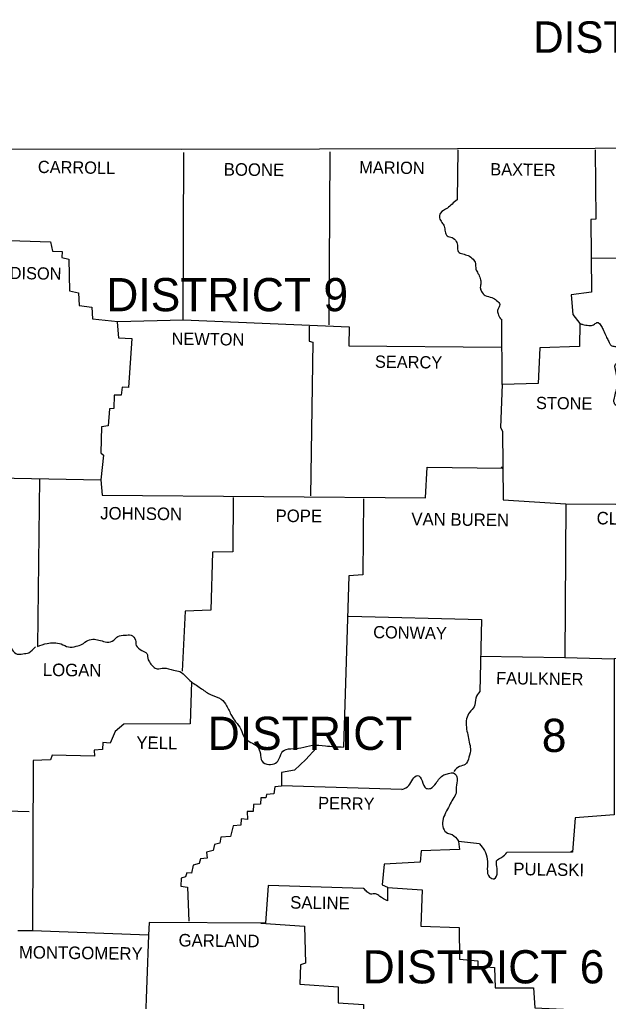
# Model space of a CAD drawing. Extents: x -12863 to 18921, y -8840 to 11152.
# Drawn here: x 11783 to 13760, y 7447 to 10747 of the extents above; entities that cross this region are included whole.
import ezdxf

# ---------------------------------------------------------------- set-up
doc = ezdxf.new("R2010")
doc.units = 0
for name, color, linetype in [('Level 1', 7, 'Continuous'), ('Level 2', 7, 'Continuous'), ('Level 3', 7, 'Continuous'), ('Level 42', 7, 'Continuous')]:
    doc.layers.add(name, color=color, linetype=linetype)

msp = doc.modelspace()

# ---------------------------------------------------------------- linework, layer by layer
at = {"layer": 'Level 1'}
for points in [[(10745.4, 10313), (12327.5, 10312), (13715.8, 10314.9), (15353.7, 10340.4), (16112.9, 10358)], [(14544.5, 10327.8), (14546.5, 10081.1), (14419.3, 10074.3), (14415.4, 9941.2), (13702.7, 9945.1)], [(11646.5, 10007.7), (11887.2, 9999.9), (11893.1, 9968.6), (11926.3, 9967.6), (11925.3, 9948), (11948.8, 9942.2), (11950.8, 9835.5), (11981.1, 9828.7), (11983.1, 9786.6), (12026.1, 9780.7), (12028.1, 9741.6), (12113.2, 9732.8), (12332.4, 9737.7), (12334.3, 10300.3)], [(12824.5, 10302.2), (12821.6, 9721.1)], [(13255, 10309.1), (13253, 10141.8)], [(13715.8, 10309.1), (13717.8, 10076.2), (13701.2, 10075.2), (13704.1, 9831.6), (13635.6, 9821.8), (13641.5, 9756.3), (13665, 9725.9), (13663, 9648.7), (13529.9, 9643.8), (13525, 9524.4), (13403.7, 9520.5), (13397.9, 9375.7), (13404.7, 9363.9), (13407.6, 9133), (13617, 9119.3), (13614.1, 8603.7), (13780.4, 8598.8), (13780.4, 8074.4), (13649.3, 8064.6), (13639.5, 7949.2), (13419.4, 7948.2)], [(10822.7, 9721.1), (11005.6, 9720.1), (11010.5, 9784.6), (11078, 9784.6), (11083.9, 9889.3), (11465.5, 9875.6), (11477.2, 9905), (11634.8, 9906), (11555.5, 9679), (11539.9, 9316), (11528.1, 9315), (11522.2, 9205.4), (11580, 9200.5), (11588.8, 9209.3), (12055.5, 9200.5), (12060.4, 9148.7)], [(12332.4, 9737.7), (12890.1, 9714.2), (12889.1, 9650.6), (13400.8, 9646.7)], [(13403.7, 9520.5), (13402.7, 9740.6)], [(12111.2, 9730.8), (12115.2, 9678), (12160.2, 9675.1), (12148.4, 9510.7), (12127.9, 9511.7), (12124, 9485.3), (12100.5, 9485.3), (12099.5, 9440.2), (12084.8, 9439.3), (12079.9, 9381.5), (12058.4, 9378.6), (12055.5, 9290.6), (12065.3, 9283.7), (12055.5, 9200.5)], [(12756, 9717.1), (12755, 9666.3), (12767.8, 9663.3), (12759.9, 9146.7)], [(12060.4, 9148.7), (13146.4, 9139.9), (13151.3, 9242.6), (13403.7, 9239.7)], [(13400.8, 9240.7), (13403.7, 9243.6)], [(11850, 9204.5), (11843.2, 8639.9)], [(12499.7, 9140.9), (12498.7, 8957.9), (12431.2, 8956.9), (12425.3, 8762.2), (12339.2, 8759.3), (12329.4, 8557.7)], [(12938, 9136), (12936, 8881.6), (12889.1, 8877.7), (12870.5, 8302.4)], [(13617, 9119.3), (14119.9, 9116.4), (14163, 9136.9), (14160, 8754.4), (14130.7, 8741.7), (14104.3, 8719.2), (14095.5, 8710.4), (14094.5, 8600.8), (13780.4, 8598.8)], [(12887.1, 8741.7), (13334.3, 8730.9), (13328.4, 8489.2)], [(11716.9, 8671.2), (11710.1, 8531.3), (11582.9, 8530.3), (11576.1, 8403.1), (11449.8, 8406.1), (11445.9, 8275), (11313.8, 8274), (11309.9, 8142.9), (11393.1, 8138), (11390.2, 8097.9), (11814.8, 8086.1)], [(13329.4, 8607.6), (13614.1, 8603.7)], [(12359.8, 8521.5), (12355.8, 8380.6), (12132.8, 8379.7), (12103.4, 8354.2), (12086.8, 8315.1), (12062.3, 8317), (12061.3, 8294.5), (12033, 8291.6), (12034, 8271.1), (11892.1, 8275), (11887.2, 8259.3), (11828.5, 8257.4), (11826.5, 7685), (11777.6, 7684)], [(12779.5, 8298.4), (12744.3, 8260.3), (12706.1, 8224.1), (12662.1, 8217.2), (12662.1, 8171.3), (12640.6, 8168.3), (12636.7, 8144.8), (12612.2, 8142.9), (12610.2, 8132.1), (12593.6, 8131.1), (12592.6, 8110.6), (12569.1, 8109.6), (12567.2, 8086.1), (12547.6, 8086.1), (12548.6, 8058.7), (12527.1, 8060.7), (12526.1, 8039.2), (12499.7, 8037.2), (12491.8, 8002), (12458.6, 7999.1), (12455.6, 7979.5), (12438, 7974.6), (12433.1, 7954), (12410.6, 7949.2), (12412.6, 7928.6), (12390.1, 7926.7), (12386.2, 7911), (12365.6, 7905.1), (12360.7, 7878.7), (12345.1, 7879.7), (12340.2, 7866), (12325.5, 7861.1), (12324.5, 7834.7), (12347, 7830.8), (12351, 7717.3)], [(13066.2, 8159.5), (12663.1, 8172.2)], [(13327.4, 7976.6), (13257, 7984.4), (13259.9, 7958), (13131.7, 7953.1), (13127.8, 7914.9), (13007.5, 7908.1), (13000.6, 7839.6), (13018.2, 7830.8), (13018.2, 7785.8)], [(13634.6, 7950.1), (13639.5, 7955)], [(12938, 7826.9), (12618.1, 7836.6), (12609.3, 7710.4), (12217.9, 7712.4), (12215.9, 7670.3)], [(13018.2, 7830.2), (13134.7, 7822.9), (13130.7, 7700.6), (13258.9, 7695.8), (13260.9, 7589.1), (13321.5, 7584.2), (13321.5, 7565.6), (13378.3, 7561.7), (13380.2, 7493.2), (13509.4, 7493.2), (13513.3, 7425.7), (13632.7, 7419.8), (13631.7, 7292.5)], [(12593.6, 7710.5), (12739.4, 7699.7), (12743.3, 7576.4), (12726.7, 7570.5), (12724.7, 7505), (12852.9, 7496.2), (12852.9, 7442.3), (12938, 7437.5), (12939, 7383.6), (12959.5, 7380.7), (12958.5, 7303.4)], [(12215.9, 7670.3), (11826.5, 7685)], [(12215.9, 7670.3), (12193.4, 7060.8)]]:
    msp.add_lwpolyline(points, dxfattribs=at)
for points in [[(13253, 10141.8), (13235.4, 10127.1), (13219.8, 10113.4), (13196.3, 10096.8), (13193.4, 10081.1), (13201.2, 10065.5), (13209, 10052.7), (13212, 10035.1), (13218.8, 10020.4), (13235.4, 10014.6), (13249.1, 10001.9), (13254, 9984.2), (13256, 9967.6), (13271.6, 9959.8), (13289.2, 9953.9), (13305.9, 9942.2), (13313.7, 9927.5), (13315.7, 9908.9), (13322.5, 9894.2), (13330.3, 9876.6), (13332.3, 9861.9), (13330.3, 9847.3), (13334.3, 9833.6), (13347, 9819.9), (13369.5, 9813), (13385.1, 9803.2), (13395.9, 9789.5), (13389, 9772.9), (13390, 9758.2), (13398.8, 9740.6)], [(13665, 9725.9), (13674.5, 9722.3), (13684.4, 9720.3), (13694.3, 9719.5), (13704.1, 9719.1), (13710.2, 9721.1), (13716.3, 9725.5), (13722.1, 9728.9), (13724.9, 9729.2), (13727.6, 9727.9), (13733.1, 9722.3), (13737.4, 9716), (13741, 9709.3), (13744.2, 9702.5), (13753, 9682.9), (13759.8, 9668.5), (13763.5, 9661.4), (13765.5, 9657.9), (13767.7, 9654.5), (13772.3, 9650.8), (13778.5, 9649.2), (13785.1, 9648), (13788.3, 9647.1), (13791.2, 9645.7), (13808.8, 9630.1), (13811.3, 9621.6), (13810.7, 9617.2), (13808.8, 9613.4), (13805.1, 9609.4), (13801.1, 9605.6), (13797, 9601.8), (13793.1, 9597.8), (13791.4, 9595.9), (13785.8, 9590.4), (13782.8, 9586.5), (13781.8, 9584.4), (13781.4, 9582.1), (13781.7, 9577.5), (13782.8, 9572.9), (13784.2, 9568.2), (13785.3, 9563.5), (13787.4, 9550.8), (13789.2, 9538.1), (13789.2, 9513.6), (13783.3, 9491.1), (13778.5, 9470.6), (13778, 9466.1), (13778.6, 9461.7), (13780.4, 9457.3), (13781.7, 9455.1), (13783.3, 9453), (13785.4, 9451.3), (13787.6, 9450.5), (13792.5, 9451.2), (13801.9, 9455.9), (13806.8, 9459.4), (13811.5, 9463.6), (13816.2, 9467.7), (13821.5, 9470.6), (13826.5, 9471.8), (13831.8, 9472.3), (13842, 9470.6), (13852.1, 9465.7), (13861.6, 9459.8), (13866.8, 9454.9), (13871.5, 9449), (13876.3, 9443.8), (13879.1, 9442.1), (13880.6, 9441.5), (13882.2, 9441.2), (13892.4, 9442.2), (13902.7, 9445.1), (13919.3, 9450), (13942.8, 9456.9), (13959.5, 9448.1), (13974.1, 9436.3), (13978.6, 9431.8), (13982.9, 9427), (13987.1, 9422.2), (13991.7, 9417.7), (14008.4, 9406), (14029.9, 9395.2), (14036.3, 9393.1), (14043, 9391.7), (14049.7, 9390.3), (14056.3, 9388.4), (14070.2, 9382.4), (14076.1, 9377.9), (14078.6, 9375.1), (14079.8, 9373.5), (14080.8, 9371.8), (14082.4, 9368.2), (14084.7, 9357.6), (14084.9, 9350.5), (14084.7, 9343.4), (14083.7, 9318.9), (14081.8, 9288.6), (14079.8, 9255.3), (14079.4, 9247.2), (14079.4, 9239.1), (14080.4, 9231), (14081.4, 9227), (14082.7, 9223), (14087.9, 9212), (14093.5, 9201.5), (14100.4, 9189), (14107.2, 9176.1), (14110.3, 9164.5), (14110.8, 9158.6), (14111.1, 9152.6), (14111.6, 9134.5), (14110.3, 9116.5)], [(11843.2, 8639.9), (11875.5, 8650.7), (11898.9, 8652.6), (11922.4, 8648.7), (11946.9, 8638.9), (11973.3, 8640.9), (11992.9, 8647.7), (12012.4, 8660.5), (12034, 8664.4), (12054.5, 8660.5), (12076, 8654.6), (12099.5, 8661.4), (12113.2, 8674.2), (12136.7, 8678.1), (12157.2, 8678.1), (12171.9, 8661.4), (12174.8, 8643.8), (12193.4, 8627.2), (12210.1, 8616.4), (12215, 8595.9), (12223.8, 8581.2), (12232.6, 8571.4), (12245.3, 8565.6), (12266.8, 8567.5), (12300.1, 8560.7), (12321.6, 8555.8), (12341.2, 8539.1), (12359.8, 8521.5)], [(11716.9, 8671.2), (11738.5, 8657.5), (11755.1, 8635), (11769.8, 8616.4), (11794.2, 8615.5), (11813.8, 8619.4), (11836.3, 8638.9)], [(12359.8, 8521.5), (12394, 8498), (12426.3, 8477.5), (12459.6, 8462.8), (12478.1, 8441.3), (12494.8, 8408), (12508.5, 8387.5), (12526.1, 8362), (12538.8, 8333.7), (12559.4, 8318), (12580.9, 8304.3), (12591.6, 8279.9), (12596.5, 8255.4), (12620, 8243.7), (12642.5, 8248.5), (12655.2, 8263.2), (12667, 8288.7), (12693.4, 8296.5), (12727.6, 8299.4), (12766.8, 8308.2), (12809.8, 8306.3), (12870.5, 8302.4)], [(13328.4, 8489.2), (13315.7, 8466.7), (13309.8, 8437.4), (13294.1, 8418.8), (13284.4, 8397.3), (13283.4, 8368.9), (13288.3, 8343.5), (13293.2, 8319), (13297.1, 8296.5), (13292.2, 8268.1), (13279.5, 8243.7), (13259.9, 8236.8), (13241.3, 8220.2)], [(13066.2, 8159.5), (13090.6, 8173.2), (13103.4, 8193.8), (13119, 8206.5), (13134.7, 8188.9), (13148.4, 8163.4), (13163, 8163.4), (13181.6, 8181), (13193.4, 8196.7), (13208, 8208.4), (13223.7, 8213.3), (13240.3, 8215.3), (13253, 8196.7), (13249.1, 8167.3), (13249.1, 8147.8), (13238.4, 8127.2), (13226.6, 8105.7), (13213.9, 8081.2), (13204.1, 8054.8), (13206.1, 8029.4), (13219.8, 8012.8), (13235.4, 8007.9), (13257, 7986.3)], [(13327.4, 7976.6), (13344, 7955), (13353.8, 7925.7), (13353.8, 7892.4), (13361.7, 7865), (13377.3, 7859.1), (13387.1, 7882.6), (13385.1, 7906.1), (13385.1, 7919.8), (13401.8, 7931.5), (13419.4, 7948.2)], [(13018.2, 7785.8), (12992.8, 7800.4), (12978.1, 7809.2), (12962.5, 7808.3), (12949.7, 7816.1), (12938, 7826.9)]]:
    msp.add_spline(points, degree=3, dxfattribs=at)

# ---------------------------------------------------------------- texts
at = {"layer": 'Level 2'}
for s, height, rotation, p in [('CARROLL', 41.09, 359.1481, (11844.1, 10231.8)), ('BOONE', 42.07, 359.4001, (12468.4, 10223)), ('MARION', 41.09, 359.1854, (12923.3, 10230.8)), ('BAXTER', 41.09, 359.2559, (13363.6, 10224)), ('MADISON', 41.09, 359.0906, (11667, 9876.6)), ('NEWTON', 41.09, 359.2717, (12293.2, 9654.5)), ('SEARCY', 41.08, 359.2527, (12976.2, 9577.2)), ('STONE', 41.08, 359.4001, (13517.2, 9438.3)), ('JOHNSON', 42.07, 359.3514, (12053.5, 9067.5)), ('POPE', 42.07, 359.6155, (12642.5, 9058.7)), ('VAN BUREN', 42.07, 359.3508, (13098.5, 9047.9)), ('CLEBURNE', 42.06, 359.2535, (13720.7, 9050.8)), ('CONWAY', 41.08, 359.0371, (12970.3, 8668.3)), ('LOGAN', 42.07, 359.3969, (11860.8, 8541.1)), ('FAULKNER', 41.09, 359.2486, (13383.2, 8513.7)), ('YELL', 42.07, 359.1987, (12174.8, 8296.5)), ('PERRY', 41.09, 359.0858, (12785.4, 8094)), ('PULASKI', 42.07, 359.053, (13440.9, 7871.9)), ('SALINE', 42.07, 359.1491, (12691.4, 7759.3)), ('GARLAND', 42.07, 359.3658, (12316.7, 7632.2)), ('MONTGOMERY', 42.07, 359.2944, (11780.5, 7592))]:
    msp.add_text(s, height=height, rotation=rotation, dxfattribs=at).set_placement(p)
at = {"layer": 'Level 3'}
for s, height, p in [('DISTRICT 9', 111.54, (12074.1, 9767)), ('DISTRICT', 111.54, (12414.6, 8292.6)), ('8', 111.5, (13536.8, 8285.7)), ('DISTRICT 6', 111.54, (12935.1, 7507.9))]:
    msp.add_text(s, height=height, dxfattribs=at).set_placement(p)
at = {"layer": 'Level 42'}
msp.add_text('DISTRICTS 2, 3, & 7 BRIDGE PRESERVATION (2022) (S)', height=105.809, dxfattribs=at).set_placement((13508, 10635.6))

doc.saveas('drawing.dxf')
